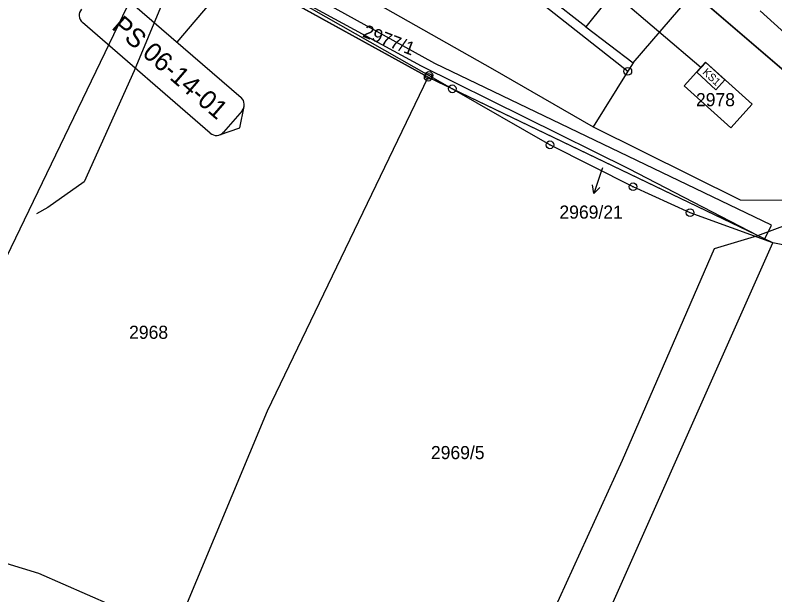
# Model space of a CAD drawing. Extents: x -620475 to -619963, y -1123010 to -1122510.
# Drawn here: x -620299.9 to -620201.4, y -1122830.6 to -1122755.4 of the extents above; entities that cross this region are included whole.
import ezdxf

# ---------------------------------------------------------------- set-up
doc = ezdxf.new("R2010")
doc.units = 0
for name, color, linetype in [('CETIN', 7, 'Continuous'), ('GasNet', 7, 'Continuous'), ('HranDP', 7, 'Continuous'), ('Hranice parcel', 7, 'Continuous'), ('Parcelní čísla', 7, 'Continuous'), ('Pop  PČ popisy', 7, 'Continuous'), ('PS 06-14-01_trasa_sdělovací_nové', 7, 'Continuous'), ('PS6-14-01_bubliny', 7, 'Continuous'), ('SEE', 7, 'Continuous'), ('Vnitřní kresba', 7, 'Continuous'), ('Vrstva 1', 7, 'Continuous'), ('Věcná břemena k části', 7, 'Continuous'), ('Značky bodu BP', 7, 'Continuous')]:
    doc.layers.add(name, color=color, linetype=linetype)

msp = doc.modelspace()

# ---------------------------------------------------------------- linework, layer by layer
at = {"layer": 'CETIN'}
msp.add_lwpolyline([(-620281.95, -1122736.09), (-620282.29, -1122736.55), (-620284.73, -1122739.75), (-620285, -1122740.28), (-620277.42, -1122745.56), (-620284.45, -1122762.59), (-620290.94, -1122776.97), (-620295.67, -1122780.3), (-620297.14, -1122781.15)], dxfattribs=at)
at = {"layer": 'GasNet'}
for points in [[(-620407.492, -1122656.883), (-620389.11, -1122672.47), (-620361.34, -1122696.38), (-620351.16, -1122708.72), (-620351, -1122709.02), (-620350.83, -1122709.39), (-620350.53, -1122710.79), (-620349.5, -1122710.44), (-620336.68, -1122702.48), (-620334.91, -1122701.4), (-620329.86, -1122698.6), (-620318.09, -1122706.99), (-620309.56, -1122715.75), (-620284.55, -1122735.89), (-620286.51, -1122738.72), (-620281.311, -1122742.821), (-620280.83, -1122743.2), (-620261.03, -1122754.43), (-620247.22, -1122761.95), (-620220.34, -1122775.27), (-620203.57, -1122783.96)], [(-620203.57, -1122783.96), (-620188.33, -1122778.28), (-620177.56, -1122770.44), (-620168.45, -1122764.1), (-620168.625, -1122763.792), (-620168.66, -1122763.73), (-620169.16, -1122764.02), (-620169.5, -1122763.44), (-620169.25, -1122763.27)], [(-620209.17, -1122785.61), (-620203.57, -1122783.96)], [(-620239.48, -1122853.1), (-620235.63, -1122844.92), (-620221.12, -1122813.09), (-620209.17, -1122785.61)], [(-620301.1, -1122826.47), (-620296.87, -1122827.75), (-620277.93, -1122836.04)]]:
    msp.add_lwpolyline(points, dxfattribs=at)
at = {"layer": 'HranDP'}
for points in [[(-620275.74, -1122741.01), (-620251.9, -1122754.44), (-620238, -1122762.33), (-620224.92, -1122769.84)], [(-620224.92, -1122769.84), (-620205.84, -1122779.33), (-620198.25, -1122779.35), (-620191.03, -1122775.11), (-620185.98, -1122780.81)]]:
    msp.add_lwpolyline(points, dxfattribs=at)
at = {"layer": 'Hranice parcel'}
for p, q in [((-620246.32, -1122763.41), (-620280.66, -1122744.45)), ((-620219.74, -1122761.53), (-620205.48, -1122744.93)), ((-620284.57, -1122752.56), (-620318.73, -1122823.4)), ((-620219.74, -1122761.53), (-620220.43, -1122762.64)), ((-620220.43, -1122762.64), (-620224.92, -1122769.84)), ((-620243.2, -1122764.91), (-620246.32, -1122763.41)), ((-620201.6, -1122784.9), (-620243.2, -1122764.91)), ((-620192.09, -1122786.79), (-620201.6, -1122784.9))]:
    msp.add_line(p, q, dxfattribs=at)
for points in [[(-620243.2, -1122764.91), (-620246.23, -1122763.17), (-620280.18, -1122743.84), (-620308.1, -1122726.09), (-620315.79, -1122721.36)], [(-620246.12, -1122731.05), (-620221.1, -1122750.9), (-620225.88, -1122756.88), (-620219.74, -1122761.53)], [(-620251.62, -1122736.54), (-620252.35, -1122737.47), (-620220.43, -1122762.64)], [(-620275.74, -1122741.01), (-620251.9, -1122754.44), (-620238, -1122762.33), (-620224.92, -1122769.84)], [(-620204.3, -1122766.9), (-620210.34, -1122761.46), (-620213.13, -1122764.54), (-620207.05, -1122769.98), (-620204.3, -1122766.9)], [(-620280.92, -1122839.64), (-620267.15, -1122806.71), (-620246.32, -1122763.41)], [(-620201.6, -1122784.9), (-620212.35, -1122780.98), (-620219.74, -1122777.62), (-620230.53, -1122772.18), (-620243.2, -1122764.91)], [(-620224.92, -1122769.84), (-620205.84, -1122779.33), (-620198.25, -1122779.35), (-620191.03, -1122775.11), (-620185.98, -1122780.81)], [(-620234.78, -1122859.86), (-620228.39, -1122845.14), (-620201.6, -1122784.9)]]:
    msp.add_lwpolyline(points, dxfattribs=at)
at = {"layer": 'Pop  PČ popisy'}
for p, q in [((-620223.7, -1122775.15), (-620223.87, -1122775.64)), ((-620223.87, -1122775.64), (-620224.847, -1122778.477)), ((-620224.847, -1122778.477), (-620224.994, -1122777.368)), ((-620224.847, -1122778.477), (-620224.048, -1122777.694))]:
    msp.add_line(p, q, dxfattribs=at)
at = {"layer": 'PS 06-14-01_trasa_sdělovací_nové'}
msp.add_lwpolyline([(-620232.134, -1122718.841), (-620235.045, -1122722.562), (-620243.025, -1122715.998), (-620248.321, -1122722.765), (-620228.504, -1122738.508), (-620211.634, -1122752.654), (-620198.933, -1122763.626), (-620190.05, -1122772.28), (-620190.33, -1122775.52), (-620181.59, -1122785.57), (-620173.131, -1122796.401), (-620158.909, -1122820.61), (-620151.64, -1122838.53)], dxfattribs=at)
at = {"layer": 'PS6-14-01_bubliny'}
msp.add_line((-620278.891, -1122758.87), (-620248.321, -1122722.765), dxfattribs=at)
for points in [[(-620287.187, -1122751.688), (-620270.596, -1122766.053)], [(-620274.586, -1122770.661), (-620291.177, -1122756.296)], [(-620273.38, -1122770.888), (-620270.747, -1122769.953), (-620270.198, -1122767.214)], [(-620270.472, -1122767.772), (-620272.866, -1122770.537)], [(-620270.472, -1122767.772), (-620272.866, -1122770.537)]]:
    msp.add_lwpolyline(points, dxfattribs=at)
for centre, start, end in [((-620290.379, -1122755.375), 139.11358, 229.11358), ((-620271.394, -1122766.974), 319.11358, 49.11358), ((-620271.394, -1122766.974), 319.11358, 348.66534), ((-620273.788, -1122769.739), 229.11358, 319.11358), ((-620273.788, -1122769.739), 289.56166, 319.11358)]:
    msp.add_arc(centre, 1.219, start, end, dxfattribs=at)
at = {"layer": 'SEE'}
msp.add_lwpolyline([(-620213.321, -1122742.288), (-620221.898, -1122752.771), (-620210.905, -1122762.159)], dxfattribs=at)
msp.add_lwpolyline([(-620210.287, -1122761.49), (-620207.838, -1122763.757), (-620209.008, -1122765.021), (-620211.457, -1122762.754)], close=True, dxfattribs=at)
at = {"layer": 'Vnitřní kresba'}
msp.add_line((-620225.88, -1122756.88), (-620250.89, -1122737.15), dxfattribs=at)
at = {"layer": 'Vrstva 1'}
for points in [[(-620173.839, -1122795.494), (-620176.67, -1122791.87), (-620181.59, -1122785.57), (-620185.43, -1122781.13), (-620190.33, -1122775.52), (-620190.05, -1122772.28), (-620198.933, -1122763.626), (-620211.634, -1122752.654), (-620228.504, -1122738.508), (-620248.321, -1122722.765)], [(-620203.242, -1122754.772), (-620197.369, -1122760.098), (-620191.907, -1122765.364), (-620186.688, -1122770.813), (-620182.207, -1122775.852), (-620181.539, -1122776.643), (-620176.088, -1122783.334), (-620170.93, -1122790.268), (-620166.464, -1122796.851), (-620162.113, -1122803.839), (-620158.128, -1122810.876), (-620154.628, -1122817.641), (-620152.992, -1122821.05), (-620149.889, -1122827.962), (-620146.963, -1122835.3)]]:
    msp.add_lwpolyline(points, dxfattribs=at)
at = {"layer": 'Věcná břemena k části'}
msp.add_lwpolyline([(-620408.148, -1122657.633), (-620389.78, -1122673.21), (-620362.07, -1122697.07), (-620350.79, -1122712.11), (-620329.91, -1122699.79), (-620318.75, -1122707.75), (-620310.23, -1122716.49), (-620285.9, -1122736.09), (-620287.87, -1122738.92), (-620280.66, -1122744.45), (-620246.32, -1122763.41), (-620202.66, -1122784.39), (-620201.79, -1122782.59), (-620245.45, -1122761.61), (-620279.7, -1122742.7), (-620285.15, -1122738.52), (-620283.23, -1122735.73), (-620308.89, -1122715.01), (-620317.45, -1122706.23), (-620329.81, -1122697.41), (-620350.27, -1122709.47), (-620360.61, -1122695.69), (-620388.48, -1122671.69), (-620406.835, -1122656.132)], dxfattribs=at)
at = {"layer": 'Značky bodu BP'}
for centre, radius in [((-620246.23, -1122763.17), 0.5), ((-620220.43, -1122762.64), 0.5), ((-620220.43, -1122762.64), 0.0303), ((-620246.32, -1122763.41), 0.5), ((-620246.32, -1122763.41), 0.0303), ((-620246.23, -1122763.17), 0.0303), ((-620243.2, -1122764.91), 0.5), ((-620243.2, -1122764.91), 0.0303), ((-620230.53, -1122772.18), 0.5), ((-620230.53, -1122772.18), 0.0303), ((-620219.74, -1122777.62), 0.5), ((-620219.74, -1122777.62), 0.0303), ((-620212.35, -1122780.98), 0.5), ((-620212.35, -1122780.98), 0.0303)]:
    msp.add_circle(centre, radius, dxfattribs=at)

# ---------------------------------------------------------------- texts
at = {"layer": 'Parcelní čísla'}
msp.add_text('2977/1', height=1.7, rotation=339, dxfattribs=at).set_placement((-620254.953, -1122758.117))
for s, p in [('2978', (-620211.587, -1122767.17)), ('2969/21', (-620229.298, -1122781.756)), ('2968', (-620285.117, -1122797.346)), ('2969/5', (-620245.965, -1122812.956))]:
    msp.add_text(s, height=1.7, dxfattribs=at).set_placement(p)
at = {"layer": 'PS6-14-01_bubliny'}
msp.add_text('PS 06-14-01', height=2.4384, rotation=319.11358, dxfattribs=at).set_placement((-620287.508, -1122757.054))
at = {"layer": 'SEE'}
msp.add_text('KS1', height=1, rotation=317.20703, dxfattribs=at).set_placement((-620210.81, -1122762.875))

doc.saveas('drawing.dxf')
